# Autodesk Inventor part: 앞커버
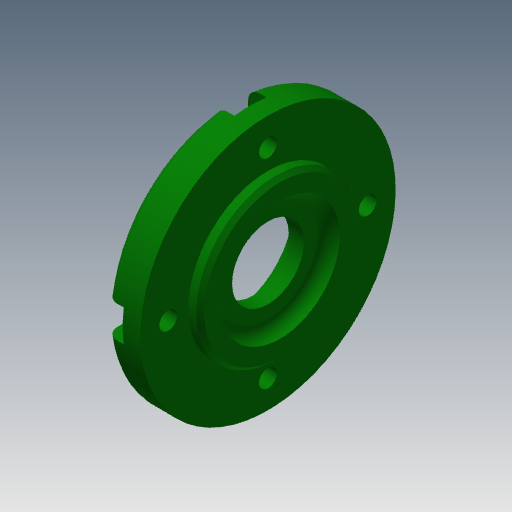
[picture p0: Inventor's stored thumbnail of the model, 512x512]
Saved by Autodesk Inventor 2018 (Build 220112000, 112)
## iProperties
Created: 2019-01
Part Number: 앞커버
Material: 알루미늄 6061
Document SubType Name: Modeling
Designer: mduedu
Density: 2.71 g/cm^3
Appearance: 진녹색
Mass: 65.0159 g
Surface Area: 90.7546 cm^2
Volume: 23.9911 cm^3
Author: mduedu
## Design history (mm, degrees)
sketch "스케치1"
  geometry: L1 (0, 0)-(9, 0); L2 (9, 0)-(9, 32); L3 (9, 32)-(0, 32); L4 (0, 32)-(0, 0); L5 (9, 0)-(12, 0); L6 (12, 0)-(12, 20); L7 (12, 20)-(9, 20); L8 (9, 20)-(9, 0)
  constraints: 16 end point, 4 parallel, 2 horizontal, 2 perpendicular
  dimensions: "d0" = 12 distance between parallel lines of L6 L4; "d2" = 64 diameter of L3 L1; "d3" = 40 diameter of L7 L5; "d4" = 3 distance between parallel lines of L6 L2
revolve "회전1" sketch "스케치1" stored, may be unused: angle "d5" = 90 deg
sketch "스케치2"
  geometry: L1 (0, -32)-(0, 32) reference; L2 (0, 32)-(9, 32) reference; L3 (9, 32)-(9, 20) reference; L4 (9, 20)-(12, 20) reference; L5 (12, 20)-(12, -20) reference; L6 (12, -20)-(9, -20) reference; L7 (9, -20)-(9, -32) reference; L8 (9, -32)-(0, -32) reference; L9 (0, 0)-(5.2, 0); L10 (5.2, 0)-(5.2, 15); L11 (5.2, 15)-(0, 15); L12 (0, 15)-(0, 0); L13 (5.2, 0)-(9, 0); L14 (9, 0)-(9, 9); L15 (9, 9)-(5.2, 9); L16 (5.2, 9)-(5.2, 0); L17 (9, 0)-(12, 0); L18 (12, 0)-(12, 15); L19 (12, 15)-(9, 15); L20 (9, 15)-(9, 0)
  constraints: 24 end point, 6 parallel, 3 horizontal, 3 perpendicular, 1 point on line
  dimensions: "d6" = 3 distance of L18.end L19.end; "d8" = 5.2 distance of L10.end L11.end; "d9" = 30 diameter of L11 L9; "d10" = 18 diameter of L15 L13; "d11" = 30 diameter of L19 L17
revolve "회전2" sketch "스케치2" stored, may be unused: angle "d12" = 90 deg
chamfer "모따기1" distance "d13" = 0.5; stored, may be unused: second distance "d14" = 2, angle "d15" = 30 deg
fillet "모깎기1" dims "d16" = 0.5
fillet "모깎기2" dims "d17" = 3
fillet "모깎기3" dims "d18" = 3
chamfer "모따기2" distance "d24" = 1; stored, may be unused: second distance "d25" = 2, angle "d26" = 45 deg
sketch "스케치3" dims "d19" = 50
  geometry: 6 further points
  constraints: 2 vertical alignment, 1 coincident, 7 other
  dimensions: "d22" = 360 deg dimension on point (0, 0) point (0, 25) (derived)
sketch "스케치4"
  geometry: 4 further points
  constraints: 4 other
hole "구멍1" sketch "스케치4" at (-25, 0), (0, -25), (25, 0), (0, 25) diameter "d27" = 4.5; stored, may be unused: countersink angle "d31" = 90 deg, drill point angle "d33" = 0 deg; dims "d28" = 6, "d29" = 8, "d30" = 4.6, "d32" = 8
sketch "스케치5"
  geometry: L1 (-4, 0)-(-4, 6.749); L2 (4, 0)-(4, 6.749); A1 r 4 centre (0, 0) between (0, 4) and (-4, 0) reference; A2 r 32 centre (0, -25) between (-4, 6.749) and (4, 6.749) reference; A3 r 4 centre (0, 0) between (-4, 0) and (4, 0); A4 r 32 centre (0, -25) between (4, 6.749) and (-4, 6.749); A5 r 4 centre (0, 0) between (4, 0) and (-4, 0); 1 further point
  constraints: 10 point on circle, 4 end point, 3 centre point, 2 coincident, 2 tangent, 1 parallel, 1 vertical
extrude "돌출1" cut sketch "스케치5" extent not by distance; stored distance "d34" = 10; taper "d35" = 0 deg
node "솔리드1"
pattern_circular "원형 패턴1" dims angle "d37" = 360 deg
node "절단 모서리 투영1"
